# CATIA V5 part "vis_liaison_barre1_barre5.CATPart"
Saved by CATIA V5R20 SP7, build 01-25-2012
Part number: skl_vis_liaison_barre2_barre5
Bounding box of the stored display mesh (mm): x -2 to 6, y 27.955 to 27.955, z 0.952 to 0.952
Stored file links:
  J:\IFMA\IAO\système avant mef\vis_liaison_barre1_barre5.CATPart
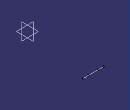
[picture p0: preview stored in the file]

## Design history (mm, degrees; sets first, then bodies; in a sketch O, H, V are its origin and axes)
Body1 (main body)
  Point1 "point_Bsecond": stored without definition
  Point2 "Point.B": stored without definition
  Line1: type PtPt, FirstPoint Point1, SecondPoint Point2
  Point3 "Point_B_vis": stored without definition
  Point4 "point_Bsecond": stored without definition
  Line2: type PtPt, FirstPoint Point3, SecondPoint Point4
